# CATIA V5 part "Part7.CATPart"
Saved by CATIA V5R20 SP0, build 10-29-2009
Part number: 1DIN7991416_DIN 7991 - M4 x 16 --- 16C
Revision: ANY
Definition: UNKNOWN
Nomenclature: 1DIN7991416_DIN 7991 - M4 x 16 --- 16C
Source: Unknown
Bounding box of the stored display mesh (mm): x 0 to 16, y -3.633 to 3.633, z -3.82 to 3.82
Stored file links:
  C:\Users\Utente\Desktop\IO LAVORO\3D X SITO CF\CUMSA\3D files PW\pw060630\pw060630_injection\Part7.CATPart
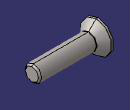
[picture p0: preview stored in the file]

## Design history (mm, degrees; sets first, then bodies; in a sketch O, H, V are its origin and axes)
Body1 "Hex" (main body)
  Solid1: solid without history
